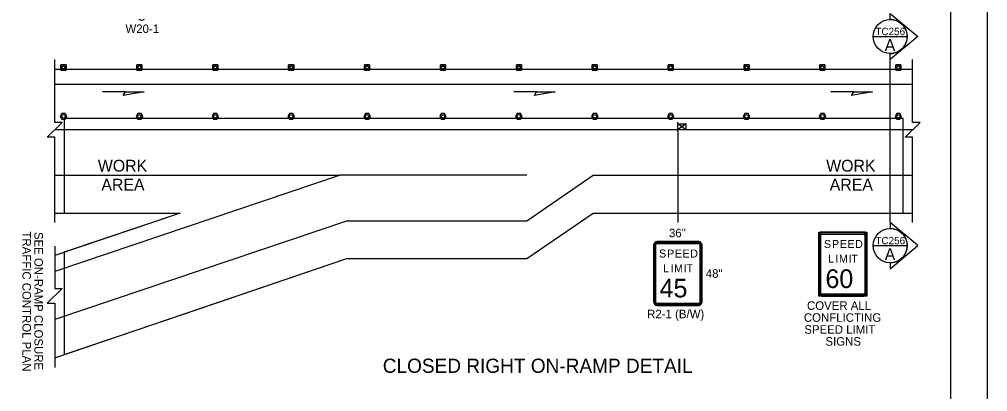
# Model space of a CAD drawing. Extents: x 99999 to 100116, y 99995 to 100013.
# Drawn here: x 100047.9 to 100056.06, y 100001.64 to 100004.79 of the extents above; entities that cross this region are included whole.
import ezdxf

# ---------------------------------------------------------------- set-up
doc = ezdxf.new("R2010")
doc.units = 0
for name, color, linetype in [('Default', 7, 'Continuous'), ('RD_MK_LineEdgeYellow', 7, 'Continuous'), ('RD_MK_LineLane', 7, 'Continuous'), ('SH_DE_DetailHeading2Text', 7, 'Continuous'), ('SH_GI_PlotLimits', 7, 'Continuous'), ('SH_GI_SectionCut', 7, 'Continuous'), ('SH_GI_SheetBorder', 7, 'Continuous'), ('TR_SN_ConstructionSigns', 7, 'Continuous'), ('TR_WZ_PortableSignMount5ftMinBlk-Wht', 7, 'Continuous'), ('TR_WZ_TallChanDevice', 7, 'Continuous'), ('TR_WZ_TrafficCone', 7, 'Continuous'), ('TR_WZ_WorkAreaLabel', 7, 'Continuous'), ('TR_WZ_WorkZoneDetails', 7, 'Continuous')]:
    doc.layers.add(name, color=color, linetype=linetype)

msp = doc.modelspace()

# ---------------------------------------------------------------- linework, layer by layer
at = {"layer": 'RD_MK_LineEdgeYellow'}
for p, q in [((100048.195, 100004.238), (100055.43, 100004.238)), ((100048.195, 100003.47), (100049.2533, 100003.47)), ((100052.1758, 100003.086), (100052.7368, 100003.47)), ((100052.7368, 100003.47), (100055.43, 100003.47)), ((100050.6655, 100003.086), (100048.195, 100002.2517)), ((100050.6655, 100003.086), (100052.1758, 100003.086)), ((100049.2943, 100003.0282), (100048.195, 100002.657))]:
    msp.add_line(p, q, dxfattribs=at)
at = {"layer": 'RD_MK_LineLane'}
for points in [[(100055.43, 100003.854), (100048.195, 100003.854)], [(100052.1758, 100003.47), (100050.6024, 100003.47)]]:
    msp.add_lwpolyline(points, dxfattribs=at)
at = {"layer": 'SH_GI_PlotLimits'}
msp.add_lwpolyline([(100039.0625, 99999.6875), (100056.0625, 99999.6875), (100056.0625, 100010.6875), (100039.0625, 100010.6875)], close=True, dxfattribs=at)
at = {"layer": 'SH_GI_SectionCut'}
for p, q in [((100055.2407, 100004.7848), (100055.2407, 100004.8357)), ((100055.2407, 100004.8357), (100055.4733, 100004.6408)), ((100055.4733, 100004.6408), (100055.2407, 100004.446)), ((100055.2407, 100004.446), (100055.2407, 100004.4968)), ((100055.2407, 100003.0699), (100055.2407, 100004.446)), ((100055.2407, 100003.07), (100055.2407, 100003.0191)), ((100055.4733, 100002.8751), (100055.2407, 100003.07)), ((100055.2407, 100002.6802), (100055.4733, 100002.8751)), ((100055.2407, 100002.7311), (100055.2407, 100002.6802))]:
    msp.add_line(p, q, dxfattribs=at)
for points in [[(100055.0967, 100004.6408), (100055.3847, 100004.6408)], [(100055.0967, 100002.8751), (100055.3847, 100002.8751)]]:
    msp.add_lwpolyline(points, dxfattribs=at)
for centre in [(100055.2407, 100004.6408), (100055.2407, 100002.8751)]:
    msp.add_circle(centre, 0.144, dxfattribs=at)
for centre in [(100055.2407, 100004.6408), (100055.2407, 100002.8751)]:
    msp.add_arc(centre, 0.144, 269.99779, 90.00221, dxfattribs=at)
at = {"layer": 'SH_GI_SheetBorder'}
msp.add_line((100055.75, 100010.375), (100055.75, 100000), dxfattribs=at)
at = {"layer": 'TR_SN_ConstructionSigns'}
for p, q in [((100054.638, 100002.4753), (100054.638, 100002.9646)), ((100054.638, 100002.9646), (100054.638, 100002.4753)), ((100054.6451, 100002.9646), (100054.6451, 100002.4753)), ((100054.6549, 100002.4753), (100054.6549, 100002.9646)), ((100054.6633, 100002.99), (100055.0177, 100002.99)), ((100055.0177, 100002.99), (100054.6633, 100002.99)), ((100055.0177, 100002.9829), (100054.6633, 100002.9829)), ((100054.6633, 100002.9731), (100055.0177, 100002.9731)), ((100055.0261, 100002.9646), (100055.0261, 100002.4753)), ((100055.036, 100002.4753), (100055.036, 100002.9646)), ((100055.043, 100002.9646), (100055.043, 100002.4753)), ((100055.043, 100002.4753), (100055.043, 100002.9646)), ((100053.2475, 100002.3953), (100053.2475, 100002.8846)), ((100053.2475, 100002.8846), (100053.2475, 100002.3953)), ((100053.2546, 100002.8846), (100053.2546, 100002.3953)), ((100053.2644, 100002.3953), (100053.2644, 100002.8846)), ((100053.2728, 100002.91), (100053.6272, 100002.91)), ((100053.6272, 100002.91), (100053.2728, 100002.91)), ((100053.6272, 100002.9029), (100053.2728, 100002.9029)), ((100053.2728, 100002.8931), (100053.6272, 100002.8931)), ((100053.6357, 100002.8846), (100053.6357, 100002.3953)), ((100053.6455, 100002.3953), (100053.6455, 100002.8846)), ((100053.6525, 100002.8846), (100053.6525, 100002.3953)), ((100053.6525, 100002.3953), (100053.6525, 100002.8846)), ((100055.0177, 100002.4668), (100054.6633, 100002.4668)), ((100053.6272, 100002.3868), (100053.2728, 100002.3868)), ((100053.2728, 100002.377), (100053.6272, 100002.377)), ((100054.6633, 100002.457), (100055.0177, 100002.457)), ((100055.0177, 100002.45), (100054.6633, 100002.45)), ((100054.6633, 100002.45), (100055.0177, 100002.45)), ((100053.6272, 100002.37), (100053.2728, 100002.37)), ((100053.2728, 100002.37), (100053.6272, 100002.37))]:
    msp.add_line(p, q, dxfattribs=at)
msp.add_lwpolyline([(100054.638, 100002.99), (100055.043, 100002.99), (100055.043, 100002.45), (100054.638, 100002.45)], close=True, dxfattribs=at)
for centre, radius, start, end in [((100048.9279, 100004.8122), 0.0338, 225.00001, 315.00001), ((100054.6633, 100002.9646), 0.0253, 90, 180), ((100054.6633, 100002.9646), 0.0253, 90, 180), ((100054.6633, 100002.9646), 0.0183, 90, 180), ((100054.6633, 100002.9646), 0.00844, 90, 180), ((100055.0177, 100002.9646), 0.0253, 0, 90), ((100055.0177, 100002.9646), 0.0253, 360, 90), ((100055.0177, 100002.9646), 0.0183, 0, 90), ((100055.0177, 100002.9646), 0.00844, 360, 90), ((100053.2728, 100002.8846), 0.0253, 90, 180), ((100053.2728, 100002.8846), 0.0253, 90, 180), ((100053.2728, 100002.8846), 0.0183, 90, 180), ((100053.2728, 100002.8846), 0.00844, 90, 180), ((100053.6272, 100002.8846), 0.0253, 360, 90), ((100053.6272, 100002.8846), 0.0253, 360, 90), ((100053.6272, 100002.8846), 0.0183, 0, 90), ((100053.6272, 100002.8846), 0.00844, 360, 90), ((100054.6633, 100002.4753), 0.0253, 180, 270), ((100054.6633, 100002.4753), 0.0253, 180, 270), ((100054.6633, 100002.4753), 0.0183, 180, 270), ((100054.6633, 100002.4753), 0.00844, 180, 270), ((100055.0177, 100002.4753), 0.0253, 270, 0), ((100055.0177, 100002.4753), 0.0183, 270, 360), ((100055.0177, 100002.4753), 0.00844, 270, 0), ((100055.0177, 100002.4753), 0.0253, 270, 0), ((100053.2728, 100002.3953), 0.0253, 180, 270), ((100053.2728, 100002.3953), 0.0253, 180, 270), ((100053.2728, 100002.3953), 0.0183, 180, 270), ((100053.2728, 100002.3953), 0.00844, 180, 270), ((100053.6272, 100002.3953), 0.0253, 270, 360), ((100053.6272, 100002.3953), 0.0183, 270, 360), ((100053.6272, 100002.3953), 0.00844, 270, 0), ((100053.6272, 100002.3953), 0.0253, 270, 360)]:
    msp.add_arc(centre, radius, start, end, dxfattribs=at)
at = {"layer": 'TR_WZ_PortableSignMount5ftMinBlk-Wht'}
for p, q in [((100053.45, 100003.838), (100053.45, 100003.918)), ((100053.5167, 100003.904), (100053.45, 100003.852)), ((100053.5167, 100003.852), (100053.45, 100003.904)), ((100053.4834, 100003.878), (100053.4834, 100003.878)), ((100053.4835, 100003.878), (100053.4835, 100003.878))]:
    msp.add_line(p, q, dxfattribs=at)
msp.add_lwpolyline([(100053.5167, 100003.904), (100053.5167, 100003.852), (100053.45, 100003.852), (100053.45, 100003.904)], close=True, dxfattribs=at)
at = {"layer": 'TR_WZ_TallChanDevice'}
for points in [[(100048.2833, 100003.9909), (100048.2555, 100003.9909), (100048.2417, 100003.9669), (100048.2555, 100003.9429), (100048.2833, 100003.9429), (100048.2971, 100003.9669)], [(100048.9233, 100003.9909), (100048.8955, 100003.9909), (100048.8817, 100003.9669), (100048.8955, 100003.9429), (100048.9233, 100003.9429), (100048.9371, 100003.9669)], [(100049.5633, 100003.9909), (100049.5355, 100003.9909), (100049.5217, 100003.9669), (100049.5355, 100003.9429), (100049.5633, 100003.9429), (100049.5771, 100003.9669)], [(100050.2033, 100003.9909), (100050.1755, 100003.9909), (100050.1617, 100003.9669), (100050.1755, 100003.9429), (100050.2033, 100003.9429), (100050.2171, 100003.9669)], [(100050.8433, 100003.9909), (100050.8155, 100003.9909), (100050.8017, 100003.9669), (100050.8155, 100003.9429), (100050.8433, 100003.9429), (100050.8571, 100003.9669)], [(100051.4833, 100003.9909), (100051.4555, 100003.9909), (100051.4417, 100003.9669), (100051.4555, 100003.9429), (100051.4833, 100003.9429), (100051.4971, 100003.9669)], [(100052.1233, 100003.9909), (100052.0955, 100003.9909), (100052.0817, 100003.9669), (100052.0955, 100003.9429), (100052.1233, 100003.9429), (100052.1371, 100003.9669)], [(100052.7633, 100003.9909), (100052.7355, 100003.9909), (100052.7217, 100003.9669), (100052.7355, 100003.9429), (100052.7633, 100003.9429), (100052.7771, 100003.9669)], [(100053.4033, 100003.9909), (100053.3755, 100003.9909), (100053.3617, 100003.9669), (100053.3755, 100003.9429), (100053.4033, 100003.9429), (100053.4171, 100003.9669)], [(100054.0433, 100003.9909), (100054.0155, 100003.9909), (100054.0017, 100003.9669), (100054.0155, 100003.9429), (100054.0433, 100003.9429), (100054.0571, 100003.9669)], [(100054.6833, 100003.9909), (100054.6555, 100003.9909), (100054.6417, 100003.9669), (100054.6555, 100003.9429), (100054.6833, 100003.9429), (100054.6971, 100003.9669)], [(100055.3233, 100003.9909), (100055.2955, 100003.9909), (100055.2817, 100003.9669), (100055.2955, 100003.9429), (100055.3233, 100003.9429), (100055.3371, 100003.9669)]]:
    msp.add_lwpolyline(points, close=True, dxfattribs=at)
for points in [[(100048.2833, 100003.9909), (100048.2555, 100003.9909), (100048.2417, 100003.9669), (100048.2555, 100003.9429), (100048.2833, 100003.9429), (100048.2971, 100003.9669), (100048.2833, 100003.9909)], [(100048.9233, 100003.9909), (100048.8955, 100003.9909), (100048.8817, 100003.9669), (100048.8955, 100003.9429), (100048.9233, 100003.9429), (100048.9371, 100003.9669), (100048.9233, 100003.9909)], [(100049.5633, 100003.9909), (100049.5355, 100003.9909), (100049.5217, 100003.9669), (100049.5355, 100003.9429), (100049.5633, 100003.9429), (100049.5771, 100003.9669), (100049.5633, 100003.9909)], [(100050.2033, 100003.9909), (100050.1755, 100003.9909), (100050.1617, 100003.9669), (100050.1755, 100003.9429), (100050.2033, 100003.9429), (100050.2171, 100003.9669), (100050.2033, 100003.9909)], [(100050.8433, 100003.9909), (100050.8155, 100003.9909), (100050.8017, 100003.9669), (100050.8155, 100003.9429), (100050.8433, 100003.9429), (100050.8571, 100003.9669), (100050.8433, 100003.9909)], [(100051.4833, 100003.9909), (100051.4555, 100003.9909), (100051.4417, 100003.9669), (100051.4555, 100003.9429), (100051.4833, 100003.9429), (100051.4971, 100003.9669), (100051.4833, 100003.9909)], [(100052.1233, 100003.9909), (100052.0955, 100003.9909), (100052.0817, 100003.9669), (100052.0955, 100003.9429), (100052.1233, 100003.9429), (100052.1371, 100003.9669), (100052.1233, 100003.9909)], [(100052.7633, 100003.9909), (100052.7355, 100003.9909), (100052.7217, 100003.9669), (100052.7355, 100003.9429), (100052.7633, 100003.9429), (100052.7771, 100003.9669), (100052.7633, 100003.9909)], [(100053.4033, 100003.9909), (100053.3755, 100003.9909), (100053.3617, 100003.9669), (100053.3755, 100003.9429), (100053.4033, 100003.9429), (100053.4171, 100003.9669), (100053.4033, 100003.9909)], [(100054.0433, 100003.9909), (100054.0155, 100003.9909), (100054.0017, 100003.9669), (100054.0155, 100003.9429), (100054.0433, 100003.9429), (100054.0571, 100003.9669), (100054.0433, 100003.9909)], [(100054.6833, 100003.9909), (100054.6555, 100003.9909), (100054.6417, 100003.9669), (100054.6555, 100003.9429), (100054.6833, 100003.9429), (100054.6971, 100003.9669), (100054.6833, 100003.9909)], [(100055.3233, 100003.9909), (100055.2955, 100003.9909), (100055.2817, 100003.9669), (100055.2955, 100003.9429), (100055.3233, 100003.9429), (100055.3371, 100003.9669), (100055.3233, 100003.9909)]]:
    msp.add_lwpolyline(points, dxfattribs=at)
for centre in [(100048.2694, 100003.9669), (100048.9094, 100003.9669), (100049.5494, 100003.9669), (100050.1894, 100003.9669), (100050.8294, 100003.9669), (100051.4694, 100003.9669), (100052.1094, 100003.9669), (100052.7494, 100003.9669), (100053.3894, 100003.9669), (100054.0294, 100003.9669), (100054.6694, 100003.9669), (100055.3094, 100003.9669)]:
    msp.add_circle(centre, 0.015, dxfattribs=at)
at = {"layer": 'TR_WZ_TrafficCone'}
for points in [[(100048.2481, 100004.4006), (100048.2907, 100004.4006), (100048.2907, 100004.358), (100048.2481, 100004.358), (100048.2481, 100004.4006)], [(100048.2481, 100004.358), (100048.2907, 100004.358), (100048.2907, 100004.4006), (100048.2481, 100004.4006), (100048.2481, 100004.358)], [(100048.8881, 100004.4006), (100048.9307, 100004.4006), (100048.9307, 100004.358), (100048.8881, 100004.358), (100048.8881, 100004.4006)], [(100048.8881, 100004.358), (100048.9307, 100004.358), (100048.9307, 100004.4006), (100048.8881, 100004.4006), (100048.8881, 100004.358)], [(100049.5281, 100004.4006), (100049.5707, 100004.4006), (100049.5707, 100004.358), (100049.5281, 100004.358), (100049.5281, 100004.4006)], [(100049.5281, 100004.358), (100049.5707, 100004.358), (100049.5707, 100004.4006), (100049.5281, 100004.4006), (100049.5281, 100004.358)], [(100050.1681, 100004.4006), (100050.2107, 100004.4006), (100050.2107, 100004.358), (100050.1681, 100004.358), (100050.1681, 100004.4006)], [(100050.1681, 100004.358), (100050.2107, 100004.358), (100050.2107, 100004.4006), (100050.1681, 100004.4006), (100050.1681, 100004.358)], [(100050.8081, 100004.4006), (100050.8507, 100004.4006), (100050.8507, 100004.358), (100050.8081, 100004.358), (100050.8081, 100004.4006)], [(100050.8081, 100004.358), (100050.8507, 100004.358), (100050.8507, 100004.4006), (100050.8081, 100004.4006), (100050.8081, 100004.358)], [(100051.4481, 100004.4006), (100051.4907, 100004.4006), (100051.4907, 100004.358), (100051.4481, 100004.358), (100051.4481, 100004.4006)], [(100051.4481, 100004.358), (100051.4907, 100004.358), (100051.4907, 100004.4006), (100051.4481, 100004.4006), (100051.4481, 100004.358)], [(100052.0881, 100004.4006), (100052.1307, 100004.4006), (100052.1307, 100004.358), (100052.0881, 100004.358), (100052.0881, 100004.4006)], [(100052.0881, 100004.358), (100052.1307, 100004.358), (100052.1307, 100004.4006), (100052.0881, 100004.4006), (100052.0881, 100004.358)], [(100052.7281, 100004.4006), (100052.7707, 100004.4006), (100052.7707, 100004.358), (100052.7281, 100004.358), (100052.7281, 100004.4006)], [(100052.7281, 100004.358), (100052.7707, 100004.358), (100052.7707, 100004.4006), (100052.7281, 100004.4006), (100052.7281, 100004.358)], [(100053.3681, 100004.4006), (100053.4107, 100004.4006), (100053.4107, 100004.358), (100053.3681, 100004.358), (100053.3681, 100004.4006)], [(100053.3681, 100004.358), (100053.4107, 100004.358), (100053.4107, 100004.4006), (100053.3681, 100004.4006), (100053.3681, 100004.358)], [(100054.0081, 100004.4006), (100054.0507, 100004.4006), (100054.0507, 100004.358), (100054.0081, 100004.358), (100054.0081, 100004.4006)], [(100054.0081, 100004.358), (100054.0507, 100004.358), (100054.0507, 100004.4006), (100054.0081, 100004.4006), (100054.0081, 100004.358)], [(100054.6481, 100004.4006), (100054.6907, 100004.4006), (100054.6907, 100004.358), (100054.6481, 100004.358), (100054.6481, 100004.4006)], [(100054.6481, 100004.358), (100054.6907, 100004.358), (100054.6907, 100004.4006), (100054.6481, 100004.4006), (100054.6481, 100004.358)], [(100055.2881, 100004.4006), (100055.3307, 100004.4006), (100055.3307, 100004.358), (100055.2881, 100004.358), (100055.2881, 100004.4006)], [(100055.2881, 100004.358), (100055.3307, 100004.358), (100055.3307, 100004.4006), (100055.2881, 100004.4006), (100055.2881, 100004.358)]]:
    msp.add_lwpolyline(points, dxfattribs=at)
for centre in [(100048.2694, 100004.3793), (100048.9094, 100004.3793), (100049.5494, 100004.3793), (100050.1894, 100004.3793), (100050.8294, 100004.3793), (100051.4694, 100004.3793), (100052.1094, 100004.3793), (100052.7494, 100004.3793), (100053.3894, 100004.3793), (100054.0294, 100004.3793), (100054.6694, 100004.3793), (100055.3094, 100004.3793)]:
    msp.add_circle(centre, 0.0133, dxfattribs=at)
at = {"layer": 'TR_WZ_WorkZoneDetails'}
for p, q in [((100048.195, 100004.366), (100055.43, 100004.366)), ((100048.7914, 100004.174), (100048.5985, 100004.174)), ((100052.2594, 100004.174), (100052.0665, 100004.174)), ((100054.9336, 100004.174), (100054.7408, 100004.174)), ((100053.45, 100003.838), (100053.45, 100003.07)), ((100049.2533, 100003.47), (100050.6024, 100003.47)), ((100050.6024, 100003.47), (100049.2943, 100003.0282)), ((100048.195, 100003.15), (100049.2533, 100003.15)), ((100049.2533, 100003.15), (100048.195, 100002.7929)), ((100052.1758, 100002.766), (100052.7368, 100003.15)), ((100052.7368, 100003.15), (100055.43, 100003.15)), ((100048.195, 100001.928), (100050.6601, 100002.766)), ((100050.6601, 100002.766), (100052.1758, 100002.766))]:
    msp.add_line(p, q, dxfattribs=at)
for points in [[(100048.195, 100003.07), (100048.195, 100003.792), (100048.131, 100003.792), (100048.259, 100003.9159), (100048.195, 100003.9159), (100048.195, 100004.446)], [(100055.43, 100003.07), (100055.43, 100003.792), (100055.366, 100003.792), (100055.494, 100003.9159), (100055.43, 100003.9159), (100055.43, 100004.446)], [(100048.195, 100002.8701), (100048.195, 100002.5136), (100048.259, 100002.5136), (100048.131, 100002.3897), (100048.195, 100002.3897), (100048.195, 100001.8453)]]:
    msp.add_lwpolyline(points, dxfattribs=at)
for points in [[(100048.9486, 100004.174), (100048.7735, 100004.1431), (100048.7914, 100004.174)], [(100052.4166, 100004.174), (100052.2415, 100004.1431), (100052.2594, 100004.174)], [(100055.0909, 100004.174), (100054.9158, 100004.1431), (100054.9336, 100004.174)], [(100048.275, 100003.95), (100048.275, 100003.15), (100049.2533, 100003.15), (100048.275, 100002.8199), (100048.275, 100002.8199), (100048.275, 100002.8199), (100048.275, 100001.9552), (100048.275, 100001.9552), (100048.275, 100001.9552), (100049.2728, 100002.2944), (100050.6601, 100002.766), (100052.1758, 100002.766), (100052.7368, 100003.15), (100055.35, 100003.15), (100055.35, 100003.95)]]:
    msp.add_lwpolyline(points, close=True, dxfattribs=at)

# ---------------------------------------------------------------- texts
at = {"layer": 'Default'}
for s, height, p in [('S', 0.0675, (100053.2914, 100002.775)), ('P', 0.0675, (100053.3596, 100002.775)), ('E', 0.0675, (100053.4257, 100002.775)), ('E', 0.0675, (100053.4899, 100002.775)), ('D', 0.0675, (100053.554, 100002.775)), ('L', 0.0675, (100053.3265, 100002.6512)), ('I', 0.0675, (100053.3886, 100002.6512)), ('M', 0.0675, (100053.4183, 100002.6512)), ('I', 0.0675, (100053.4993, 100002.6512)), ('T', 0.0675, (100053.5229, 100002.6512)), ('45', 0.1575, (100053.2965, 100002.4375))]:
    msp.add_text(s, height=height, dxfattribs=at).set_placement(p)
at = {"layer": 'SH_DE_DetailHeading2Text'}
msp.add_text('CLOSED RIGHT ON-RAMP DETAIL', height=0.12, rotation=360, dxfattribs=at).set_placement((100050.9618, 100001.8009))
at = {"layer": 'SH_GI_SectionCut'}
for p in [(100055.1158, 100004.6524), (100055.1158, 100002.8867)]:
    msp.add_text('TC256', height=0.0625, dxfattribs=at).set_placement(p)
for p in [(100055.1945, 100004.5188), (100055.1945, 100002.7531)]:
    msp.add_text('A', height=0.1, rotation=359.99005, dxfattribs=at).set_placement(p)
at = {"layer": 'TR_SN_ConstructionSigns'}
msp.add_text('W20-1', height=0.072, rotation=360, dxfattribs=at).set_placement((100048.7921, 100004.6705))
for s, height, p in [('36"', 0.072, (100053.3753, 100002.946)), ('S', 0.0675, (100054.6819, 100002.855)), ('P', 0.0675, (100054.7501, 100002.855)), ('E', 0.0675, (100054.8162, 100002.855)), ('E', 0.0675, (100054.8803, 100002.855)), ('D', 0.0675, (100054.9445, 100002.855)), ('L', 0.0675, (100054.717, 100002.7312)), ('I', 0.0675, (100054.7791, 100002.7312)), ('M', 0.0675, (100054.8088, 100002.7312)), ('I', 0.0675, (100054.8898, 100002.7312)), ('T', 0.0675, (100054.9134, 100002.7312)), ('60', 0.1575, (100054.6949, 100002.5175)), ('COVER ALL', 0.072, (100054.5392, 100002.333)), ('CONFLICTING', 0.072, (100054.5128, 100002.2322)), ('SPEED LIMIT', 0.072, (100054.5168, 100002.1314)), ('SIGNS', 0.072, (100054.6947, 100002.0306))]:
    msp.add_text(s, height=height, dxfattribs=at).set_placement(p)
at = {"layer": 'TR_WZ_WorkAreaLabel'}
for s, p in [('WORK', (100048.559, 100003.5)), ('WORK', (100054.7013, 100003.5)), ('AREA', (100048.5887, 100003.34)), ('AREA', (100054.7309, 100003.34))]:
    msp.add_text(s, height=0.1, dxfattribs=at).set_placement(p)
at = {"layer": 'TR_WZ_WorkZoneDetails'}
for s, p in [('TRAFFIC CONTROL PLAN', (100047.923, 100002.9948)), ('SEE ON-RAMP CLOSURE', (100048.0238, 100002.9908))]:
    msp.add_text(s, height=0.072, rotation=270, dxfattribs=at).set_placement(p)
for s, p in [('48"', (100053.6858, 100002.604)), ('R2-1 (B/W)', (100053.1913, 100002.262))]:
    msp.add_text(s, height=0.072, dxfattribs=at).set_placement(p)

doc.saveas('drawing.dxf')
